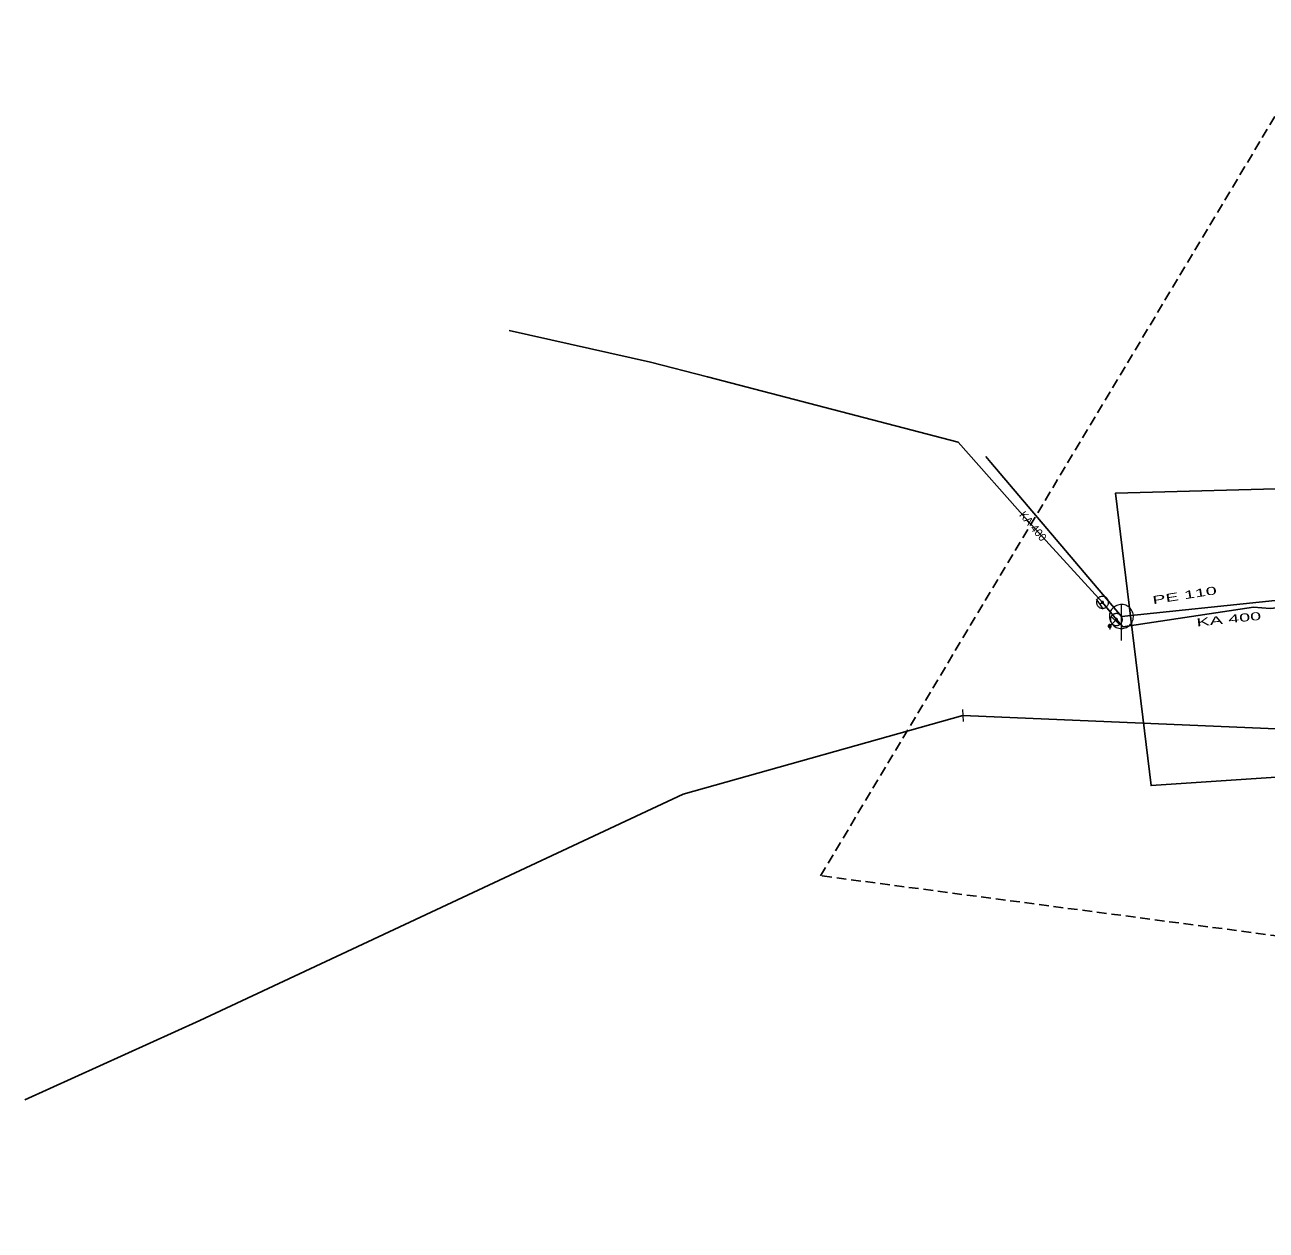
# Model space of a CAD drawing. Extents: x -687593 to -687108, y -975254 to -974717.
# Drawn here: x -687593.3 to -687489.9, y -974944.2 to -974843.8 of the extents above; entities that cross this region are included whole.
import ezdxf
from ezdxf.enums import TextEntityAlignment as Align

# ---------------------------------------------------------------- set-up
doc = ezdxf.new("R2010")
doc.units = 0
doc.header["$LTSCALE"] = 0.27
doc.linetypes.add('MEDIUM_DASHED', pattern=[4.5, 3, -1.5])
for name, color, linetype, lineweight in [('1', 7, 'Continuous', 25), ('14', 7, 'Continuous', 13), ('17', 7, 'Continuous', 25), ('22', 7, 'Continuous', 13), ('34', 7, 'Continuous', 13), ('47', 7, 'Continuous', 13), ('63', 7, 'MEDIUM_DASHED', 25), ('9', 7, 'Continuous', 13)]:
    doc.layers.add(name, color=color, linetype=linetype, lineweight=lineweight)

msp = doc.modelspace()

# ---------------------------------------------------------------- linework, layer by layer
at = {"layer": '1'}
msp.add_lwpolyline([(-687190.553, -975166.941), (-687164.86, -975177.861), (-687155.924, -975158.837), (-687125.348, -975155.541), (-687124.826, -975139.621), (-687173.065, -975131.89), (-687231.828, -975028.025), (-687222.959, -975015.464), (-687237.898, -975004.026), (-687247.4, -975009.654), (-687276.892, -974983.781), (-687453.606, -974886.044), (-687460.232, -974860.45), (-687474.874, -974858.564), (-687482.889, -974882.272), (-687502.421, -974882.802), (-687499.452, -974907.164), (-687464.42, -974904.824), (-687331.319, -974973.728), (-687252.566, -975037.916), (-687192.379, -975151.48)], close=True, dxfattribs=at)
at = {"layer": '14'}
for p, q in [((-687503.5, -974891.899), (-687503.71, -974892.05)), ((-687502.43, -974893.42), (-687502.899, -974893.879)), ((-687502.346, -974893.334), (-687502.43, -974893.42))]:
    msp.add_line(p, q, dxfattribs=at)
at = {"layer": '14', "lineweight": 25}
for points in [[(-687501.93, -974893.079), (-687512.815, -974880.241), (-687513.23, -974879.76)], [(-687484.239, -974891.23), (-687489.129, -974891.737), (-687501.93, -974893.079)]]:
    msp.add_lwpolyline(points, dxfattribs=at)
at = {"layer": '17'}
for points in [[(-687503.5, -974891.899), (-687509.719, -974885.1), (-687515.528, -974878.557), (-687536.41, -974873.109), (-687541.16, -974871.89), (-687552.93, -974869.25)], [(-687488.395, -974892.307), (-687489.541, -974892.416), (-687490.936, -974892.292), (-687501.809, -974893.949), (-687502.346, -974893.334), (-687503.5, -974891.899)], [(-687515.147, -974901.318), (-687538.446, -974907.872), (-687578.716, -974926.75), (-687593.299, -974933.349)], [(-687397.965, -974929.018), (-687440.137, -974904.525), (-687515.147, -974901.318)]]:
    msp.add_lwpolyline(points, dxfattribs=at)
at = {"layer": '22'}
msp.add_line((-687501.93, -974895.079), (-687501.929, -974892.079), dxfattribs=at)
msp.add_lwpolyline([(-687500.93, -974893.079), (-687500.935, -974892.97), (-687500.953, -974892.862), (-687500.983, -974892.756), (-687501.023, -974892.655), (-687501.075, -974892.558), (-687501.137, -974892.468), (-687501.209, -974892.385), (-687501.289, -974892.311), (-687501.377, -974892.245), (-687501.471, -974892.19), (-687501.571, -974892.145), (-687501.676, -974892.112), (-687501.783, -974892.09), (-687501.892, -974892.08), (-687502.002, -974892.082), (-687502.11, -974892.096), (-687502.217, -974892.121), (-687502.32, -974892.158), (-687502.418, -974892.207), (-687502.51, -974892.265), (-687502.596, -974892.334), (-687502.673, -974892.411), (-687502.742, -974892.497), (-687502.801, -974892.589), (-687502.849, -974892.687), (-687502.886, -974892.79), (-687502.912, -974892.897), (-687502.926, -974893.005), (-687502.929, -974893.115), (-687502.919, -974893.224), (-687502.898, -974893.331), (-687502.864, -974893.435), (-687502.82, -974893.535), (-687502.765, -974893.63), (-687502.699, -974893.718), (-687502.625, -974893.798), (-687502.542, -974893.87), (-687502.452, -974893.932), (-687502.356, -974893.984), (-687502.254, -974894.025), (-687502.149, -974894.055), (-687502.041, -974894.073), (-687501.931, -974894.079), (-687501.822, -974894.073), (-687501.714, -974894.055), (-687501.609, -974894.026), (-687501.507, -974893.985), (-687501.41, -974893.933), (-687501.32, -974893.871), (-687501.237, -974893.8), (-687501.162, -974893.72), (-687501.097, -974893.632), (-687501.041, -974893.538), (-687500.997, -974893.438), (-687500.963, -974893.334), (-687500.941, -974893.226), (-687500.931, -974893.117)], close=True, dxfattribs=at)
at = {"layer": '34'}
for p, q in [((-687503.418, -974892.456), (-687504, -974891.642)), ((-687502.073, -974893.77), (-687502.785, -974893.068)), ((-687515.18, -974900.819), (-687515.114, -974901.816))]:
    msp.add_line(p, q, dxfattribs=at)
at = {"layer": '47'}
for points in [[(-687503.813, -974891.509), (-687503.852, -974891.544), (-687503.887, -974891.583), (-687503.917, -974891.625), (-687503.944, -974891.67), (-687503.966, -974891.718), (-687503.982, -974891.768), (-687503.992, -974891.819), (-687503.998, -974891.871), (-687503.999, -974891.923), (-687503.994, -974891.975), (-687503.983, -974892.027), (-687503.966, -974892.076), (-687503.946, -974892.124), (-687503.919, -974892.169), (-687503.889, -974892.212), (-687503.854, -974892.251), (-687503.815, -974892.286), (-687503.772, -974892.317), (-687503.728, -974892.343), (-687503.68, -974892.365), (-687503.63, -974892.381), (-687503.579, -974892.392), (-687503.527, -974892.398), (-687503.475, -974892.398), (-687503.423, -974892.393), (-687503.371, -974892.382), (-687503.321, -974892.366), (-687503.274, -974892.345), (-687503.229, -974892.318), (-687503.186, -974892.288), (-687503.147, -974892.253), (-687503.112, -974892.214), (-687503.08, -974892.172), (-687503.055, -974892.127), (-687503.033, -974892.079), (-687503.017, -974892.03), (-687503.005, -974891.978), (-687503, -974891.926), (-687503, -974891.874), (-687503.005, -974891.822), (-687503.016, -974891.77), (-687503.031, -974891.721), (-687503.053, -974891.673), (-687503.08, -974891.628), (-687503.11, -974891.585), (-687503.145, -974891.546), (-687503.184, -974891.511), (-687503.225, -974891.48), (-687503.271, -974891.454), (-687503.319, -974891.432), (-687503.368, -974891.416), (-687503.419, -974891.405), (-687503.471, -974891.399), (-687503.524, -974891.399), (-687503.576, -974891.404), (-687503.628, -974891.415), (-687503.676, -974891.431), (-687503.725, -974891.452), (-687503.77, -974891.479)], [(-687503.551, -974891.835), (-687503.558, -974891.84), (-687503.563, -974891.847), (-687503.568, -974891.853), (-687503.572, -974891.861), (-687503.576, -974891.869), (-687503.578, -974891.877), (-687503.581, -974891.885), (-687503.582, -974891.894), (-687503.581, -974891.902), (-687503.581, -974891.911), (-687503.579, -974891.92), (-687503.576, -974891.928), (-687503.572, -974891.935), (-687503.569, -974891.943), (-687503.563, -974891.95), (-687503.558, -974891.957), (-687503.551, -974891.962), (-687503.545, -974891.967), (-687503.537, -974891.971), (-687503.529, -974891.975), (-687503.521, -974891.977), (-687503.513, -974891.98), (-687503.504, -974891.981), (-687503.495, -974891.981), (-687503.487, -974891.98), (-687503.478, -974891.978), (-687503.47, -974891.975), (-687503.463, -974891.971), (-687503.455, -974891.968), (-687503.448, -974891.962), (-687503.441, -974891.957), (-687503.436, -974891.95), (-687503.431, -974891.944), (-687503.427, -974891.936), (-687503.423, -974891.928), (-687503.42, -974891.921), (-687503.418, -974891.912), (-687503.417, -974891.903), (-687503.417, -974891.894), (-687503.418, -974891.886), (-687503.42, -974891.877), (-687503.423, -974891.869), (-687503.427, -974891.862), (-687503.43, -974891.854), (-687503.436, -974891.847), (-687503.441, -974891.84), (-687503.448, -974891.835), (-687503.454, -974891.83), (-687503.462, -974891.826), (-687503.47, -974891.822), (-687503.477, -974891.819), (-687503.486, -974891.817), (-687503.495, -974891.816), (-687503.503, -974891.817), (-687503.512, -974891.817), (-687503.521, -974891.819), (-687503.529, -974891.822), (-687503.536, -974891.826), (-687503.544, -974891.829)], [(-687502.674, -974892.957), (-687502.711, -974892.993), (-687502.745, -974893.033), (-687502.774, -974893.077), (-687502.799, -974893.122), (-687502.818, -974893.171), (-687502.833, -974893.222), (-687502.841, -974893.273), (-687502.845, -974893.325), (-687502.843, -974893.377), (-687502.836, -974893.429), (-687502.823, -974893.481), (-687502.805, -974893.529), (-687502.783, -974893.576), (-687502.754, -974893.621), (-687502.722, -974893.662), (-687502.686, -974893.699), (-687502.646, -974893.733), (-687502.602, -974893.762), (-687502.557, -974893.787), (-687502.508, -974893.806), (-687502.457, -974893.821), (-687502.405, -974893.83), (-687502.353, -974893.833), (-687502.301, -974893.832), (-687502.25, -974893.824), (-687502.198, -974893.811), (-687502.149, -974893.794), (-687502.103, -974893.771), (-687502.058, -974893.742), (-687502.017, -974893.71), (-687501.98, -974893.674), (-687501.946, -974893.634), (-687501.916, -974893.591), (-687501.892, -974893.545), (-687501.873, -974893.496), (-687501.858, -974893.446), (-687501.849, -974893.394), (-687501.845, -974893.342), (-687501.847, -974893.289), (-687501.855, -974893.238), (-687501.868, -974893.186), (-687501.885, -974893.138), (-687501.908, -974893.091), (-687501.937, -974893.046), (-687501.969, -974893.005), (-687502.005, -974892.968), (-687502.045, -974892.934), (-687502.088, -974892.905), (-687502.134, -974892.88), (-687502.183, -974892.861), (-687502.233, -974892.846), (-687502.284, -974892.837), (-687502.337, -974892.834), (-687502.389, -974892.836), (-687502.441, -974892.843), (-687502.493, -974892.856), (-687502.541, -974892.874), (-687502.588, -974892.896), (-687502.633, -974892.925)], [(-687502.399, -974893.272), (-687502.406, -974893.278), (-687502.411, -974893.284), (-687502.416, -974893.291), (-687502.42, -974893.299), (-687502.423, -974893.307), (-687502.425, -974893.315), (-687502.427, -974893.324), (-687502.428, -974893.332), (-687502.427, -974893.341), (-687502.426, -974893.349), (-687502.424, -974893.358), (-687502.421, -974893.366), (-687502.417, -974893.373), (-687502.413, -974893.381), (-687502.407, -974893.387), (-687502.401, -974893.394), (-687502.395, -974893.399), (-687502.388, -974893.404), (-687502.38, -974893.408), (-687502.372, -974893.411), (-687502.364, -974893.413), (-687502.355, -974893.415), (-687502.347, -974893.416), (-687502.338, -974893.416), (-687502.33, -974893.414), (-687502.321, -974893.412), (-687502.313, -974893.409), (-687502.306, -974893.405), (-687502.298, -974893.401), (-687502.292, -974893.395), (-687502.285, -974893.389), (-687502.28, -974893.383), (-687502.275, -974893.376), (-687502.271, -974893.368), (-687502.268, -974893.36), (-687502.265, -974893.352), (-687502.264, -974893.343), (-687502.263, -974893.335), (-687502.263, -974893.326), (-687502.265, -974893.318), (-687502.267, -974893.309), (-687502.27, -974893.301), (-687502.274, -974893.294), (-687502.278, -974893.286), (-687502.284, -974893.28), (-687502.29, -974893.273), (-687502.296, -974893.268), (-687502.303, -974893.263), (-687502.311, -974893.259), (-687502.319, -974893.256), (-687502.327, -974893.253), (-687502.336, -974893.252), (-687502.344, -974893.251), (-687502.353, -974893.252), (-687502.361, -974893.253), (-687502.37, -974893.255), (-687502.378, -974893.258), (-687502.385, -974893.262), (-687502.393, -974893.266)]]:
    msp.add_lwpolyline(points, close=True, dxfattribs=at)
at = {"layer": '63'}
msp.add_lwpolyline([(-687526.998, -974914.677), (-687484.572, -974843.781), (-687484.572, -974843.781), (-687425.956, -974881.183), (-687425.956, -974881.183), (-687214.941, -975003.438), (-687214.941, -975003.438), (-687108.316, -975140.766), (-687108.316, -975140.766), (-687138.461, -975189.333), (-687138.461, -975189.333), (-687208.242, -975184.867), (-687208.242, -975184.867), (-687273.556, -975040.84), (-687273.556, -975040.84), (-687454.985, -974924.168), (-687454.985, -974924.168)], close=True, dxfattribs=at)
at = {"layer": '9'}
msp.add_line((-687502.9, -974894.005), (-687502.9, -974894.13), dxfattribs=at)
for points in [[(-687503.026, -974893.878), (-687503.025, -974893.891), (-687503.023, -974893.904), (-687503.02, -974893.917), (-687503.015, -974893.929), (-687503.009, -974893.941), (-687503.002, -974893.952), (-687502.994, -974893.962), (-687502.984, -974893.972), (-687502.974, -974893.98), (-687502.963, -974893.987), (-687502.951, -974893.993), (-687502.939, -974893.998), (-687502.926, -974894.001), (-687502.913, -974894.003), (-687502.9, -974894.005), (-687502.887, -974894.005), (-687502.874, -974894.003), (-687502.861, -974894), (-687502.849, -974893.995), (-687502.837, -974893.989), (-687502.826, -974893.982), (-687502.816, -974893.974), (-687502.806, -974893.964), (-687502.798, -974893.954), (-687502.791, -974893.943), (-687502.785, -974893.931), (-687502.78, -974893.919), (-687502.777, -974893.906), (-687502.775, -974893.893), (-687502.773, -974893.88), (-687502.774, -974893.867), (-687502.776, -974893.854), (-687502.779, -974893.841), (-687502.784, -974893.829), (-687502.79, -974893.817), (-687502.797, -974893.806), (-687502.805, -974893.796), (-687502.815, -974893.786), (-687502.825, -974893.778), (-687502.836, -974893.771), (-687502.848, -974893.765), (-687502.86, -974893.76), (-687502.873, -974893.757), (-687502.886, -974893.755), (-687502.899, -974893.752), (-687502.912, -974893.753), (-687502.925, -974893.755), (-687502.938, -974893.758), (-687502.95, -974893.763), (-687502.962, -974893.769), (-687502.973, -974893.776), (-687502.983, -974893.784), (-687502.993, -974893.794), (-687503.001, -974893.804), (-687503.008, -974893.815), (-687503.014, -974893.827), (-687503.019, -974893.839), (-687503.022, -974893.852), (-687503.024, -974893.865)], [(-687503.006, -974893.878), (-687503.006, -974893.889), (-687503.004, -974893.9), (-687503.001, -974893.911), (-687502.997, -974893.921), (-687502.992, -974893.931), (-687502.986, -974893.94), (-687502.979, -974893.949), (-687502.971, -974893.957), (-687502.962, -974893.964), (-687502.953, -974893.97), (-687502.943, -974893.975), (-687502.933, -974893.979), (-687502.922, -974893.982), (-687502.911, -974893.984), (-687502.9, -974893.984), (-687502.889, -974893.986), (-687502.878, -974893.984), (-687502.867, -974893.981), (-687502.857, -974893.977), (-687502.847, -974893.972), (-687502.838, -974893.966), (-687502.829, -974893.959), (-687502.821, -974893.951), (-687502.814, -974893.942), (-687502.808, -974893.933), (-687502.803, -974893.923), (-687502.799, -974893.913), (-687502.796, -974893.902), (-687502.794, -974893.891), (-687502.793, -974893.88), (-687502.793, -974893.869), (-687502.795, -974893.858), (-687502.798, -974893.847), (-687502.802, -974893.837), (-687502.807, -974893.827), (-687502.813, -974893.818), (-687502.82, -974893.809), (-687502.828, -974893.801), (-687502.837, -974893.794), (-687502.846, -974893.788), (-687502.856, -974893.783), (-687502.866, -974893.779), (-687502.877, -974893.776), (-687502.888, -974893.774), (-687502.899, -974893.772), (-687502.91, -974893.772), (-687502.921, -974893.774), (-687502.932, -974893.777), (-687502.942, -974893.781), (-687502.952, -974893.786), (-687502.961, -974893.792), (-687502.97, -974893.799), (-687502.978, -974893.807), (-687502.985, -974893.816), (-687502.991, -974893.825), (-687502.996, -974893.835), (-687503, -974893.845), (-687503.003, -974893.856), (-687503.005, -974893.867)], [(-687502.987, -974893.878), (-687502.986, -974893.887), (-687502.985, -974893.896), (-687502.982, -974893.905), (-687502.979, -974893.913), (-687502.975, -974893.921), (-687502.97, -974893.929), (-687502.964, -974893.936), (-687502.958, -974893.942), (-687502.951, -974893.948), (-687502.943, -974893.953), (-687502.935, -974893.957), (-687502.927, -974893.96), (-687502.918, -974893.963), (-687502.909, -974893.964), (-687502.9, -974893.967), (-687502.891, -974893.966), (-687502.882, -974893.965), (-687502.873, -974893.962), (-687502.865, -974893.959), (-687502.857, -974893.955), (-687502.849, -974893.95), (-687502.842, -974893.944), (-687502.836, -974893.938), (-687502.83, -974893.931), (-687502.825, -974893.923), (-687502.821, -974893.915), (-687502.818, -974893.907), (-687502.815, -974893.898), (-687502.814, -974893.889), (-687502.812, -974893.88), (-687502.813, -974893.871), (-687502.814, -974893.862), (-687502.817, -974893.853), (-687502.82, -974893.845), (-687502.824, -974893.837), (-687502.829, -974893.829), (-687502.835, -974893.822), (-687502.841, -974893.816), (-687502.848, -974893.81), (-687502.856, -974893.805), (-687502.864, -974893.801), (-687502.872, -974893.798), (-687502.881, -974893.795), (-687502.89, -974893.794), (-687502.899, -974893.791), (-687502.908, -974893.792), (-687502.917, -974893.793), (-687502.926, -974893.796), (-687502.934, -974893.799), (-687502.942, -974893.803), (-687502.95, -974893.808), (-687502.957, -974893.814), (-687502.963, -974893.82), (-687502.969, -974893.827), (-687502.974, -974893.835), (-687502.978, -974893.843), (-687502.981, -974893.851), (-687502.984, -974893.86), (-687502.985, -974893.869)], [(-687502.967, -974893.878), (-687502.967, -974893.885), (-687502.965, -974893.892), (-687502.964, -974893.899), (-687502.961, -974893.905), (-687502.958, -974893.911), (-687502.954, -974893.917), (-687502.95, -974893.923), (-687502.945, -974893.928), (-687502.939, -974893.932), (-687502.933, -974893.936), (-687502.927, -974893.939), (-687502.921, -974893.942), (-687502.914, -974893.943), (-687502.907, -974893.945), (-687502.9, -974893.945), (-687502.893, -974893.947), (-687502.886, -974893.945), (-687502.879, -974893.944), (-687502.873, -974893.941), (-687502.866, -974893.938), (-687502.861, -974893.934), (-687502.855, -974893.93), (-687502.85, -974893.925), (-687502.846, -974893.919), (-687502.842, -974893.913), (-687502.839, -974893.907), (-687502.836, -974893.901), (-687502.834, -974893.894), (-687502.833, -974893.887), (-687502.832, -974893.88), (-687502.832, -974893.873), (-687502.833, -974893.866), (-687502.835, -974893.859), (-687502.838, -974893.853), (-687502.841, -974893.846), (-687502.845, -974893.841), (-687502.849, -974893.835), (-687502.854, -974893.83), (-687502.86, -974893.826), (-687502.865, -974893.822), (-687502.872, -974893.819), (-687502.878, -974893.816), (-687502.885, -974893.814), (-687502.892, -974893.813), (-687502.899, -974893.811), (-687502.906, -974893.811), (-687502.913, -974893.812), (-687502.92, -974893.814), (-687502.926, -974893.817), (-687502.932, -974893.82), (-687502.938, -974893.824), (-687502.944, -974893.828), (-687502.949, -974893.833), (-687502.953, -974893.839), (-687502.957, -974893.844), (-687502.96, -974893.851), (-687502.963, -974893.857), (-687502.964, -974893.864), (-687502.966, -974893.871)], [(-687502.947, -974893.878), (-687502.947, -974893.883), (-687502.946, -974893.888), (-687502.945, -974893.893), (-687502.943, -974893.897), (-687502.941, -974893.902), (-687502.938, -974893.906), (-687502.935, -974893.909), (-687502.931, -974893.913), (-687502.928, -974893.916), (-687502.924, -974893.919), (-687502.919, -974893.921), (-687502.915, -974893.923), (-687502.91, -974893.924), (-687502.905, -974893.925), (-687502.9, -974893.925), (-687502.895, -974893.927), (-687502.89, -974893.926), (-687502.885, -974893.925), (-687502.881, -974893.923), (-687502.876, -974893.921), (-687502.872, -974893.918), (-687502.868, -974893.915), (-687502.865, -974893.911), (-687502.862, -974893.908), (-687502.859, -974893.904), (-687502.857, -974893.899), (-687502.855, -974893.895), (-687502.854, -974893.89), (-687502.853, -974893.885), (-687502.853, -974893.88), (-687502.852, -974893.875), (-687502.853, -974893.87), (-687502.854, -974893.865), (-687502.856, -974893.861), (-687502.858, -974893.856), (-687502.861, -974893.852), (-687502.864, -974893.848), (-687502.867, -974893.845), (-687502.871, -974893.842), (-687502.875, -974893.839), (-687502.88, -974893.837), (-687502.884, -974893.835), (-687502.889, -974893.834), (-687502.894, -974893.833), (-687502.899, -974893.831), (-687502.904, -974893.831), (-687502.909, -974893.832), (-687502.914, -974893.833), (-687502.918, -974893.835), (-687502.923, -974893.837), (-687502.927, -974893.84), (-687502.93, -974893.843), (-687502.934, -974893.846), (-687502.937, -974893.85), (-687502.94, -974893.854), (-687502.942, -974893.859), (-687502.944, -974893.863), (-687502.945, -974893.868), (-687502.946, -974893.873)], [(-687502.927, -974893.878), (-687502.927, -974893.881), (-687502.927, -974893.884), (-687502.926, -974893.886), (-687502.925, -974893.889), (-687502.924, -974893.892), (-687502.922, -974893.894), (-687502.92, -974893.896), (-687502.918, -974893.898), (-687502.916, -974893.9), (-687502.914, -974893.902), (-687502.911, -974893.903), (-687502.908, -974893.904), (-687502.906, -974893.905), (-687502.903, -974893.905), (-687502.9, -974893.905), (-687502.897, -974893.907), (-687502.894, -974893.907), (-687502.891, -974893.906), (-687502.889, -974893.905), (-687502.886, -974893.904), (-687502.884, -974893.902), (-687502.881, -974893.9), (-687502.879, -974893.898), (-687502.878, -974893.896), (-687502.876, -974893.894), (-687502.875, -974893.891), (-687502.874, -974893.888), (-687502.873, -974893.886), (-687502.873, -974893.883), (-687502.871, -974893.88), (-687502.872, -974893.877), (-687502.872, -974893.874), (-687502.873, -974893.871), (-687502.874, -974893.869), (-687502.875, -974893.866), (-687502.877, -974893.864), (-687502.878, -974893.861), (-687502.88, -974893.859), (-687502.883, -974893.858), (-687502.885, -974893.856), (-687502.888, -974893.855), (-687502.89, -974893.854), (-687502.893, -974893.853), (-687502.896, -974893.853), (-687502.899, -974893.85), (-687502.902, -974893.851), (-687502.905, -974893.851), (-687502.907, -974893.852), (-687502.91, -974893.853), (-687502.913, -974893.854), (-687502.915, -974893.856), (-687502.917, -974893.857), (-687502.919, -974893.859), (-687502.921, -974893.862), (-687502.923, -974893.864), (-687502.924, -974893.867), (-687502.925, -974893.869), (-687502.926, -974893.872), (-687502.926, -974893.875)], [(-687502.908, -974893.878), (-687502.908, -974893.879), (-687502.908, -974893.88), (-687502.907, -974893.88), (-687502.907, -974893.881), (-687502.907, -974893.882), (-687502.906, -974893.883), (-687502.906, -974893.883), (-687502.905, -974893.884), (-687502.905, -974893.884), (-687502.904, -974893.885), (-687502.903, -974893.885), (-687502.902, -974893.885), (-687502.902, -974893.886), (-687502.901, -974893.886), (-687502.9, -974893.886), (-687502.899, -974893.887), (-687502.898, -974893.887), (-687502.898, -974893.887), (-687502.897, -974893.887), (-687502.896, -974893.887), (-687502.895, -974893.886), (-687502.895, -974893.886), (-687502.894, -974893.885), (-687502.894, -974893.885), (-687502.893, -974893.884), (-687502.893, -974893.883), (-687502.892, -974893.882), (-687502.892, -974893.882), (-687502.892, -974893.881), (-687502.891, -974893.88), (-687502.891, -974893.879), (-687502.891, -974893.878), (-687502.891, -974893.878), (-687502.892, -974893.877), (-687502.892, -974893.876), (-687502.893, -974893.875), (-687502.893, -974893.875), (-687502.894, -974893.874), (-687502.894, -974893.874), (-687502.895, -974893.873), (-687502.896, -974893.873), (-687502.897, -974893.872), (-687502.897, -974893.872), (-687502.898, -974893.872), (-687502.899, -974893.87), (-687502.9, -974893.87), (-687502.901, -974893.87), (-687502.901, -974893.87), (-687502.902, -974893.871), (-687502.903, -974893.871), (-687502.904, -974893.872), (-687502.904, -974893.872), (-687502.905, -974893.873), (-687502.905, -974893.873), (-687502.906, -974893.874), (-687502.906, -974893.875), (-687502.906, -974893.876), (-687502.907, -974893.876), (-687502.907, -974893.877)]]:
    msp.add_lwpolyline(points, close=True, dxfattribs=at)
msp.add_lwpolyline([(-687502.869, -974894.097), (-687502.9, -974894.13), (-687502.931, -974894.095)], dxfattribs=at)

# ---------------------------------------------------------------- texts
at = {"layer": '1'}
msp.add_text('KA 400', height=0.6667, rotation=310, dxfattribs=at).set_placement((-687509.5439, -974885.7625), align=Align.CENTER)
msp.add_text('KA 400', height=0.6667, rotation=310, dxfattribs=at).set_placement((-687509.5439, -974885.7625), align=Align.CENTER)
msp.add_text('KA 400', height=0.6667, rotation=310, dxfattribs=at).set_placement((-687509.5439, -974885.7625), align=Align.CENTER)
msp.add_text('KA 400', height=0.6667, rotation=310, dxfattribs=at).set_placement((-687509.5439, -974885.7625), align=Align.CENTER)
msp.add_text('KA 400', height=0.6667, rotation=310, dxfattribs=at).set_placement((-687509.5439, -974885.7625), align=Align.CENTER)
at = {"layer": '1', "width": 1.85}
for s, rotation, p in [('PE 110', 9, (-687496.6161, -974891.633)), ('PE 110', 9, (-687496.6161, -974891.633)), ('PE 110', 9, (-687496.6161, -974891.633)), ('PE 110', 9, (-687496.6161, -974891.633)), ('PE 110', 9, (-687496.6161, -974891.633)), ('KA 400', 6, (-687492.9498, -974893.6285)), ('KA 400', 6, (-687492.9498, -974893.6285)), ('KA 400', 6, (-687492.9498, -974893.6285)), ('KA 400', 6, (-687492.9498, -974893.6285)), ('KA 400', 6, (-687492.9498, -974893.6285))]:
    msp.add_text(s, height=0.6667, rotation=rotation, dxfattribs=at).set_placement(p, align=Align.CENTER)

doc.saveas('drawing.dxf')
